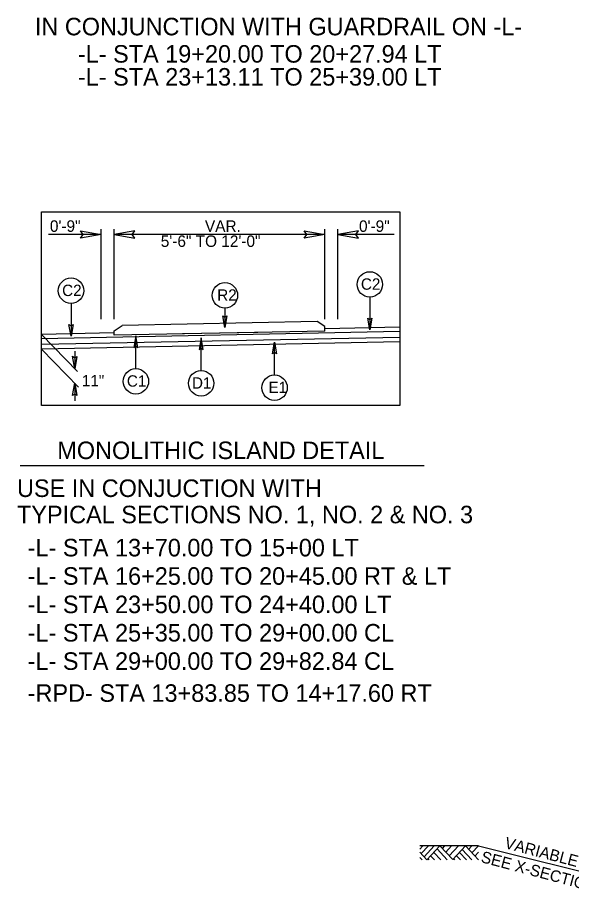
# Model space of a CAD drawing. Extents: x 1901582 to 1902252, y 193723 to 194156.
# Drawn here: x 1901984.3 to 1902015.9, y 193953.9 to 194003.9 of the extents above; entities that cross this region are included whole.
import ezdxf

# ---------------------------------------------------------------- set-up
doc = ezdxf.new("R2010")
doc.units = 0
for name, color, linetype in [('Old_Level_1', 7, 'Continuous'), ('Old_Level_11', 7, 'Continuous'), ('Old_Level_20', 7, 'Continuous'), ('Typical Terminator CELL', 7, 'Continuous')]:
    doc.layers.add(name, color=color, linetype=linetype)

# ---------------------------------------------------------------- blocks, each defined once
blk = doc.blocks.new('TERMINATOR')
at = {"layer": 'Typical Terminator CELL'}
blk.add_lwpolyline([(-0.469, 0.081), (0, 0), (-0.471, -0.083), (-0.411, 0)], close=True, dxfattribs=at)

msp = doc.modelspace()

# ---------------------------------------------------------------- linework, layer by layer
at = {"layer": 'Old_Level_1'}
for p, q in [((1901989.113, 193986.7), (1901989.113, 193991.824)), ((1901989.863, 193986.7), (1901989.863, 193991.824)), ((1902001.864, 193986.7), (1902001.864, 193991.824)), ((1902002.614, 193986.7), (1902002.614, 193991.824)), ((1901989.113, 193991.532), (1901986.111, 193991.532)), ((1902001.864, 193991.532), (1901989.863, 193991.532)), ((1902005.824, 193991.532), (1902002.614, 193991.532)), ((1901989.863, 193986.031), (1901990.322, 193986.332)), ((1902001.433, 193986.554), (1901990.322, 193986.332)), ((1902001.864, 193986.271), (1902001.433, 193986.554)), ((1902001.864, 193986.017), (1902001.864, 193986.271)), ((1902006.141, 193986.231), (1902001.864, 193986.146)), ((1901989.863, 193985.906), (1901985.716, 193985.823)), ((1901985.716, 193985.823), (1901987.764, 193983.707)), ((1902006.141, 193985.981), (1901985.721, 193985.573)), ((1902006.148, 193985.648), (1901985.728, 193985.24)), ((1901989.863, 193985.777), (1901989.863, 193986.031)), ((1902001.864, 193986.017), (1901989.863, 193985.777)), ((1901998.042, 193985.941), (1901993.756, 193985.855)), ((1902006.153, 193985.398), (1901985.733, 193984.99)), ((1901985.716, 193984.99), (1901987.822, 193982.814)), ((1901987.607, 193984.869), (1901987.607, 193983.869)), ((1901987.607, 193983.036), (1901987.607, 193982.036))]:
    msp.add_line(p, q, dxfattribs=at)
msp.add_lwpolyline([(1902006.141, 193981.772), (1901985.716, 193981.772), (1901985.716, 193992.823), (1902006.141, 193992.823)], close=True, dxfattribs=at)
for points in [[(1902010.631, 193956.647), (1902007.289, 193956.647)], [(1902010.631, 193956.647), (1902018.631, 193954.647)]]:
    msp.add_lwpolyline(points, dxfattribs=at)
at = {"layer": 'Old_Level_11'}
for p, q in [((1901987.396, 193987.593), (1901987.396, 193985.719)), ((1902004.436, 193987.953), (1902004.436, 193986.079)), ((1901996.174, 193987.326), (1901996.174, 193986.216)), ((1901991.095, 193983.871), (1901991.095, 193985.745)), ((1901994.816, 193983.759), (1901994.816, 193985.633)), ((1901999.003, 193983.509), (1901999.003, 193985.383)), ((1901984.491, 193978.352), (1902007.534, 193978.352)), ((1902007.459, 193956.647), (1902007.289, 193956.464)), ((1902007.779, 193956.647), (1902007.365, 193956.203)), ((1902008.112, 193956.647), (1902007.532, 193956.024)), ((1902008.434, 193956.646), (1902007.693, 193955.85)), ((1902009.165, 193955.86), (1902008.434, 193956.646)), ((1902008.698, 193956.647), (1902008.565, 193956.504)), ((1902009.1, 193956.647), (1902008.767, 193956.288)), ((1902009.498, 193956.647), (1902008.965, 193956.074)), ((1902009.889, 193956.639), (1902009.165, 193955.86)), ((1902010.631, 193955.842), (1902009.889, 193956.639)), ((1902010.256, 193956.647), (1902010.069, 193956.446)), ((1902010.631, 193956.647), (1902010.256, 193956.244)), ((1902007.693, 193955.85), (1902007.289, 193956.285)), ((1902008.119, 193955.842), (1902007.902, 193956.075)), ((1902008.485, 193955.842), (1902008.085, 193956.271)), ((1902008.855, 193955.842), (1902008.269, 193956.47)), ((1902009.601, 193955.842), (1902009.374, 193956.085)), ((1902009.948, 193955.842), (1902009.547, 193956.271)), ((1902010.257, 193955.842), (1902009.703, 193956.438)), ((1902010.631, 193956.285), (1902010.425, 193956.063)), ((1902007.423, 193955.842), (1902007.289, 193955.985)), ((1902007.824, 193955.842), (1902007.755, 193955.916)), ((1902009.29, 193955.842), (1902009.219, 193955.918))]:
    msp.add_line(p, q, dxfattribs=at)
for points in [[(1901996.29, 193986.888), (1901996.174, 193986.216), (1901996.055, 193986.891), (1901996.174, 193986.806)], [(1902004.551, 193986.75), (1902004.436, 193986.079), (1902004.316, 193986.754), (1902004.436, 193986.668)], [(1901987.511, 193986.391), (1901987.396, 193985.719), (1901987.276, 193986.394), (1901987.396, 193986.309)], [(1901991.21, 193985.074), (1901991.095, 193985.745), (1901990.975, 193985.07), (1901991.095, 193985.156)], [(1901994.931, 193984.962), (1901994.816, 193985.633), (1901994.696, 193984.958), (1901994.816, 193985.044)], [(1901998.887, 193984.711), (1901999.003, 193985.383), (1901999.122, 193984.708), (1901999.003, 193984.793)]]:
    msp.add_lwpolyline(points, close=True, dxfattribs=at)
for centre in [(1902004.436, 193988.678), (1901987.396, 193988.319), (1901996.174, 193988.051), (1901991.095, 193983.146), (1901994.816, 193983.034), (1901999.003, 193982.783)]:
    msp.add_circle(centre, 0.725, dxfattribs=at)
at = {"layer": 'Typical Terminator CELL'}
for points in [[(1901987.942, 193991.733), (1901989.113, 193991.532), (1901987.935, 193991.323), (1901988.085, 193991.532)], [(1901991.035, 193991.733), (1901989.863, 193991.532), (1901991.042, 193991.323), (1901990.892, 193991.532)], [(1902000.692, 193991.733), (1902001.864, 193991.532), (1902000.685, 193991.323), (1902000.835, 193991.532)], [(1902003.785, 193991.733), (1902002.614, 193991.532), (1902003.792, 193991.323), (1902003.642, 193991.532)]]:
    msp.add_lwpolyline(points, close=True, dxfattribs=at)

# ---------------------------------------------------------------- block references
at = {"layer": 'Old_Level_1', "xscale": 1.5, "yscale": 1.5}
for p, rotation in [((1901987.607, 193983.869), -90), ((1901987.607, 193983.036), 90)]:
    msp.add_blockref('TERMINATOR', p, dxfattribs=dict(at, rotation=rotation))

# ---------------------------------------------------------------- texts
at = {"layer": 'Old_Level_1'}
for s, p in [('0\'-9"', (1901986.192, 193991.676)), ('VAR.', (1901995.034, 193991.675)), ('0\'-9"', (1902003.82, 193991.673)), ('5\'-6" TO 12\'-0"', (1901992.515, 193990.815))]:
    msp.add_text(s, height=0.656, dxfattribs=at).set_placement(p)
for s, rotation, p in [('VARIABLE', 345.2456, (1902012.074, 193956.526)), ('SEE X-SECTIONS', 345.1369, (1902010.728, 193955.726))]:
    msp.add_text(s, height=0.656, rotation=rotation, dxfattribs=at).set_placement(p)
at = {"layer": 'Old_Level_11'}
for s, p in [('IN CONJUNCTION WITH GUARDRAIL ON -L-', (1901985.335, 194002.886)), ('-L- STA 19+20.00 TO 20+27.94 LT', (1901987.789, 194001.329)), ('-L- STA 23+13.11 TO 25+39.00 LT', (1901987.789, 194000.018)), ('MONOLITHIC ISLAND DETAIL', (1901986.613, 193978.711)), ('USE IN CONJUCTION WITH', (1901984.317, 193976.549)), ('TYPICAL SECTIONS NO. 1, NO. 2 & NO. 3', (1901984.317, 193975.049)), ('-L- STA 13+70.00 TO 15+00 LT', (1901984.926, 193973.159)), ('-L- STA 16+25.00 TO 20+45.00 RT & LT', (1901984.926, 193971.541)), ('-L- STA 23+50.00 TO 24+40.00 LT', (1901984.926, 193969.922)), ('-L- STA 25+35.00 TO 29+00.00 CL', (1901984.926, 193968.304)), ('-L- STA 29+00.00 TO 29+82.84 CL', (1901984.926, 193966.686)), ('-RPD- STA 13+83.85 TO 14+17.60 RT', (1901984.926, 193964.864))]:
    msp.add_text(s, height=1, dxfattribs=at).set_placement(p)
at = {"layer": 'Old_Level_20'}
for s, p in [('C2', (1901986.889, 193988.012)), ('C2', (1902003.929, 193988.372)), ('R2', (1901995.735, 193987.745)), ('11"', (1901988.016, 193982.859)), ('C1', (1901990.582, 193982.842)), ('D1', (1901994.294, 193982.73)), ('E1', (1901998.658, 193982.48))]:
    msp.add_text(s, height=0.6491, dxfattribs=at).set_placement(p)

doc.saveas('drawing.dxf')
